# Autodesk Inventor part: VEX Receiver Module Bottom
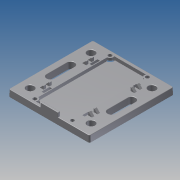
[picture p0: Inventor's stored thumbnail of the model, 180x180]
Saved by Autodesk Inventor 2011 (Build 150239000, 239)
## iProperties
Created: 2010-06
Part Number: VEX Receiver Module Bottom
Document SubType Name: Modeling
Designer: Phil
Density: 1 g/cm^3
Author: Phil
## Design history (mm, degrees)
sketch "Sketch1"
  geometry: L1 (3.075, 20.07)-(3.075, 32.77); L2 (7.425, 32.77)-(7.425, 20.07); L3 (-1.07, 1.07)-(-1.07, 51.77); L4 (15.923, 40.533)-(15.923, 2); L5 (31.17, 41.733)-(17.123, 41.733); L6 (0, 52.84)-(48.6, 52.84); L7 (17.123, 0.8)-(31.17, 0.8); L8 (48.6, 0)-(0, 0); L9 (41.175, 20.07)-(41.175, 32.77); L10 (45.525, 32.77)-(45.525, 20.07); L11 (32.37, 2)-(32.37, 40.533); L12 (49.67, 51.77)-(49.67, 1.07); A1 r 2.845 centre (5.25, 32.77) between (8.095, 32.77) and (2.405, 32.77); A2 r 2.845 centre (43.35, 32.77) between (46.195, 32.77) and (40.505, 32.77); A3 r 2.845 centre (5.25, 20.07) between (2.405, 20.07) and (8.095, 20.07); A4 r 2.845 centre (43.35, 20.07) between (40.505, 20.07) and (46.195, 20.07); A5 r 1.2 centre (31.17, 2) between (31.17, 0.8) and (32.37, 2); A6 r 3.133 centre (36, 2.92) between (39.099, 2.458) and (37.649, 5.584); 170 further points; 10 other entities
  constraints: 24 end point, 24 horizontal alignment, 20 vertical alignment, 12 point on circle, 6 centre point, 421 other
extrude "Extrusion1" new body sketch "Sketch1" distance "d0" = 4.0132; taper "d1" = -2 deg
sketch "Sketch2"
  geometry: L1 (-48.6, 52.699)-(0, 52.699) reference; L2 (-29.875, 52.699)-(-18.725, 52.699); L3 (-18.725, 52.699)-(-18.725, 51.252); L4 (-18.725, 51.252)-(-29.875, 51.252); L5 (-29.875, 51.252)-(-29.875, 52.699); 3 further points
  constraints: 8 end point, 3 midpoint, 2 parallel, 1 coincident, 1 horizontal, 1 perpendicular
  dimensions: "d2" = 11.1506 distance of L3.end L4.end; "d3" = 1.4478 distance of L4.end L2.start
extrude "Extrusion2" join sketch "Sketch2" distance "d4" = 2.54; taper "d5" = -2 deg
sketch "Sketch3"
  geometry: L1 (0.735, 1.074)-(0.735, 51.774); L2 (-12.735, 47.931)-(-12.735, 4.918); L3 (-36.27, 13.924)-(-36.27, 8.924); L4 (-37.77, 13.924)-(-36.27, 13.924); L5 (-38.135, 15.709)-(-38.135, 14.14); L6 (-38.135, 10.64)-(-40.52, 10.64); L7 (-40.52, 12.209)-(-38.135, 12.209); L8 (-38.135, 14.14)-(-40.52, 14.14); L9 (-40.52, 15.709)-(-38.135, 15.709); L10 (-40.52, 15.709)-(-40.52, 14.14); L11 (-40.781, 32.774)-(-40.781, 20.074); L12 (-45.86, 20.074)-(-45.86, 32.774); L13 (-40.52, 12.209)-(-40.52, 10.64); L14 (-35.805, 4.918)-(-35.805, 47.931); L15 (-49.276, 51.774)-(-49.276, 1.074); L16 (-26.346, 52.48)-(-48.57, 52.48); L17 (-24.664, 52.424)-(-25.135, 51.129); L18 (-21.456, 52.424)-(-24.664, 52.424); L19 (-20.985, 51.129)-(-21.456, 52.424); L20 (0.03, 52.48)-(-22.195, 52.48); L21 (-29.57, 1.574)-(-18.97, 1.574); L22 (-37.77, 8.924)-(-37.77, 13.924); L23 (-38.135, 37.14)-(-40.52, 37.14); L24 (-40.52, 38.709)-(-40.52, 37.14); L25 (-38.135, 38.709)-(-38.135, 37.14); L26 (-40.52, 38.709)-(-38.135, 38.709); L27 (-38.135, 40.64)-(-40.52, 40.64); L28 (-40.52, 42.209)-(-40.52, 40.64); L29 (-38.135, 42.209)-(-38.135, 40.64); L30 (-40.52, 42.209)-(-38.135, 42.209); L31 (-10.405, 10.64)-(-10.405, 12.209); L32 (-10.405, 12.209)-(-8.02, 12.209); L33 (-8.02, 10.64)-(-8.02, 12.209); L34 (-8.02, 10.64)-(-10.405, 10.64); L35 (-10.405, 14.14)-(-10.405, 15.709); L36 (-10.405, 15.709)-(-8.02, 15.709); L37 (-8.02, 14.14)-(-8.02, 15.709); L38 (-8.02, 14.14)-(-10.405, 14.14); L39 (-12.27, 8.924)-(-12.27, 13.924); L40 (-10.77, 13.924)-(-10.77, 8.924); L41 (-10.77, 8.924)-(-12.27, 8.924); L42 (-12.27, 13.924)-(-10.77, 13.924); L43 (-7.76, 20.074)-(-7.76, 32.774); L44 (-2.681, 32.774)-(-2.681, 20.074); L45 (-10.405, 37.14)-(-10.405, 38.709); L46 (-10.405, 38.709)-(-8.02, 38.709); L47 (-8.02, 37.14)-(-8.02, 38.709); L48 (-8.02, 37.14)-(-10.405, 37.14); L49 (-10.405, 40.64)-(-10.405, 42.209); L50 (-10.405, 42.209)-(-8.02, 42.209); L51 (-8.02, 40.64)-(-8.02, 42.209); L52 (-8.02, 40.64)-(-10.405, 40.64); L53 (-36.27, 38.924)-(-37.77, 38.924); L54 (-10.77, 38.924)-(-12.27, 38.924); L55 (-37.77, 38.924)-(-37.77, 43.924); L56 (-37.77, 43.924)-(-36.27, 43.924); L57 (-36.27, 43.924)-(-36.27, 38.924); L58 (-34.29, 51.009)-(-14.251, 51.009); L59 (-12.27, 38.924)-(-12.27, 43.924); L60 (-10.77, 43.924)-(-10.77, 38.924); L61 (-12.27, 43.924)-(-10.77, 43.924); L62 (-36.27, 8.924)-(-37.77, 8.924); L63 (-14.364, 2.04)-(-34.177, 2.04); L64 (-38.135, 12.209)-(-38.135, 10.64); C1 r 1.1 at (-12.57, 2.924); C2 r 1.1 at (-12.57, 49.924); C3 r 1.1 at (-35.97, 49.924); C4 r 1.1 at (-35.97, 2.924); A1 r 2 centre (-12.57, 2.924) between (-12.735, 4.918) and (-14.364, 2.04); A2 r 2 centre (-35.97, 49.924) between (-35.805, 47.931) and (-34.29, 51.009); A3 r 2 centre (-12.57, 49.924) between (-14.251, 51.009) and (-12.735, 47.931); A4 r 2 centre (-35.97, 2.924) between (-34.177, 2.04) and (-35.805, 4.918); 28 further points; 2 other entities
  constraints: 128 end point, 8 centre point, 8 point on circle, 76 other
extrude "Extrusion3" cut sketch "Sketch3" distance "d6" = 2.0066; taper "d7" = 0 deg
extrude "Extrusion4" cut sketch "Sketch3" distance "d8" = 2.4892; taper "d9" = 0 deg
workplane "Work Plane1"
sketch "Sketch4"
  geometry: L1 (0, 0)-(2.385, 0) reference; L2 (0.401, 2.007)-(0.045, 2.007); L3 (0.045, 2.007)-(0, 0); L4 (0.401, 2.007)-(2.385, 0); 1 further point
  constraints: 6 end point, 1 parallel
  dimensions: "d11" = 2.0066 vertical distance of L2.end L1.start; "d12" = 0.3556 distance of L2.start L2.end
extrude "Extrusion5" join sketch "Sketch4" distance "d13" = 1.4986; taper "d14" = 0 deg
pattern_linear "Rectangular Pattern1" dims "d17" = 3.5052
pattern_linear "Rectangular Pattern2" dims "d20" = 26.4922
workplane "Work Plane2"
mirror "Mirror1"
extrude "Extrusion6" cut sketch "Sketch1" distance "d21" = 2.032; taper "d22" = 0 deg
extrude "Extrusion7" cut sketch "Sketch1" distance "d23" = 2.4892; taper "d24" = 0 deg
hole "Hole1" sketch "Sketch3" diameter "d25" = 2.2098; stored, may be unused: countersink angle "d29" = 82 deg, drill point angle "d31" = 118 deg; dims "d26" = 19.05, "d27" = 9.525, "d28" = 6.35, "d30" = 25.4
fillet "Fillet1" dims "d32" = 0.254
fillet "Fillet2" dims "d33" = 0.254
fillet "Fillet3" dims "d34" = 0.1016
fillet "Fillet5" dims "d36" = 0.254
fillet "Fillet8" dims "d39" = 0.1016
extrude "Extrusion8" cut sketch "Sketch1" distance "d40" = 0.508; taper "d41" = 0 deg
fillet "Fillet9" dims "d42" = 0.127
workplane "Work Plane3"
body "Solid1"
other parameters: "d10" = 90 deg
